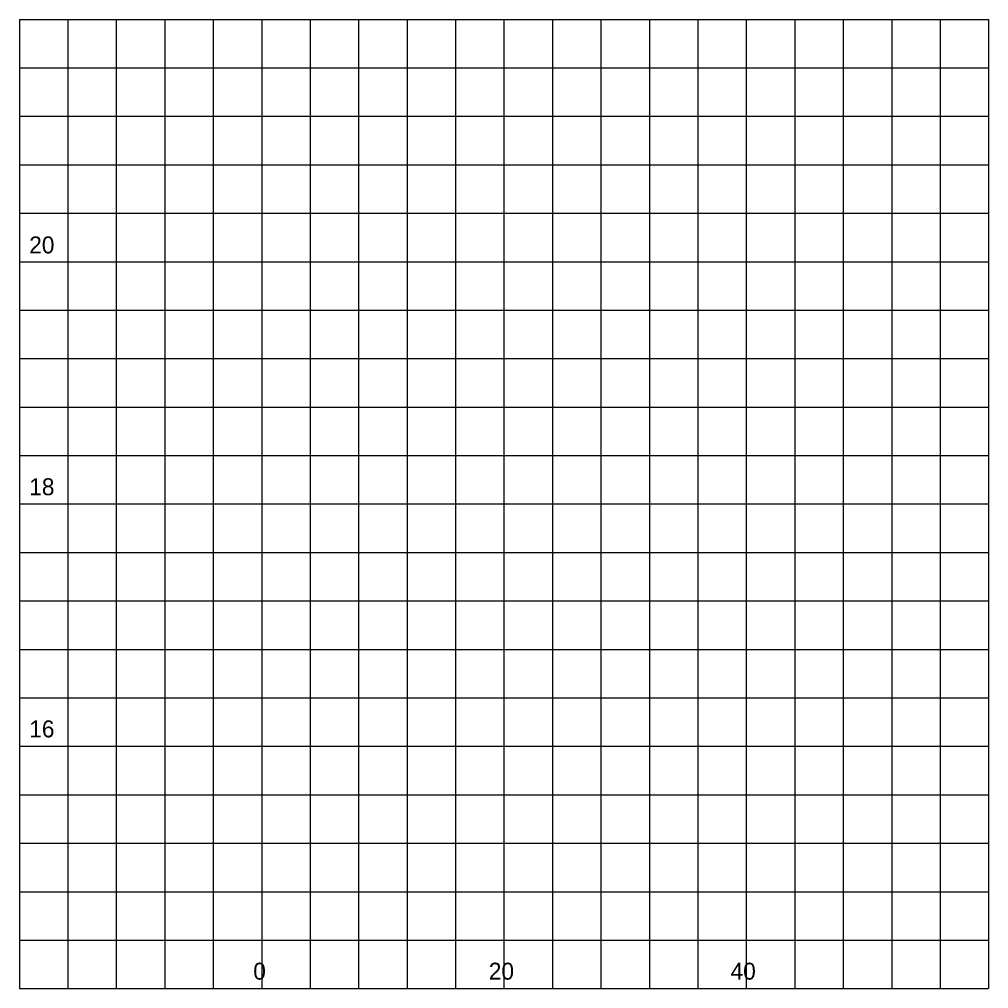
# Model space of a CAD drawing. Extents: x 127723 to 128378, y 21426 to 23736.
# Drawn here: x 127739.5 to 127819.5, y 21531 to 21611 of the extents above; entities that cross this region are included whole.
import ezdxf

# ---------------------------------------------------------------- set-up
doc = ezdxf.new("R2010")
doc.units = 0
for name, color, linetype in [('GroundCover', 7, 'Continuous'), ('Miscellaneous0', 7, 'Continuous'), ('SheetBorder_dp', 7, 'Continuous')]:
    doc.layers.add(name, color=color, linetype=linetype)

msp = doc.modelspace()

# ---------------------------------------------------------------- linework, layer by layer
at = {"layer": 'Miscellaneous0'}
for p, q in [((127743.537, 21610.984), (127743.537, 21530.984)), ((127747.537, 21610.984), (127747.537, 21530.984)), ((127751.537, 21610.984), (127751.537, 21530.984)), ((127755.537, 21610.984), (127755.537, 21530.984)), ((127763.537, 21610.984), (127763.537, 21530.984)), ((127767.537, 21610.984), (127767.537, 21530.984)), ((127771.537, 21610.984), (127771.537, 21530.984)), ((127775.537, 21610.984), (127775.537, 21530.984)), ((127783.537, 21610.984), (127783.537, 21530.984)), ((127787.537, 21610.984), (127787.537, 21530.984)), ((127791.537, 21610.984), (127791.537, 21530.984)), ((127795.537, 21610.984), (127795.537, 21530.984)), ((127803.537, 21610.984), (127803.537, 21530.984)), ((127807.537, 21610.984), (127807.537, 21530.984)), ((127811.537, 21610.984), (127811.537, 21530.984)), ((127815.537, 21610.984), (127815.537, 21530.984)), ((127739.537, 21606.984), (127819.537, 21606.984)), ((127739.537, 21602.984), (127819.537, 21602.984)), ((127739.537, 21598.984), (127819.537, 21598.984)), ((127739.537, 21594.984), (127819.537, 21594.984)), ((127739.537, 21586.984), (127819.537, 21586.984)), ((127739.537, 21582.984), (127819.537, 21582.984)), ((127739.537, 21578.984), (127819.537, 21578.984)), ((127739.537, 21574.984), (127819.537, 21574.984)), ((127739.537, 21566.984), (127819.537, 21566.984)), ((127739.537, 21562.984), (127819.537, 21562.984)), ((127739.537, 21558.984), (127819.537, 21558.984)), ((127739.537, 21554.984), (127819.537, 21554.984)), ((127739.537, 21546.984), (127819.537, 21546.984)), ((127739.537, 21542.984), (127819.537, 21542.984)), ((127739.537, 21538.984), (127819.537, 21538.984)), ((127739.537, 21534.984), (127819.537, 21534.984))]:
    msp.add_line(p, q, dxfattribs=at)
at = {"layer": 'SheetBorder_dp'}
for p, q in [((127739.537, 21610.984), (127819.537, 21610.984)), ((127739.537, 21610.984), (127739.537, 21530.984)), ((127759.537, 21610.984), (127759.537, 21550.984)), ((127759.537, 21610.984), (127759.537, 21530.984)), ((127779.537, 21610.984), (127779.537, 21530.984)), ((127799.537, 21610.984), (127799.537, 21530.984)), ((127819.537, 21610.984), (127819.537, 21530.984)), ((127739.537, 21590.984), (127819.537, 21590.984)), ((127739.537, 21570.984), (127819.537, 21570.984)), ((127739.537, 21550.984), (127819.537, 21550.984)), ((127739.537, 21550.984), (127819.537, 21550.984)), ((127739.537, 21530.984), (127819.537, 21530.984))]:
    msp.add_line(p, q, dxfattribs=at)

# ---------------------------------------------------------------- texts
at = {"layer": 'GroundCover'}
for s, p in [('20', (127740.349, 21591.668)), ('18', (127740.349, 21571.705)), ('16', (127740.349, 21551.722)), ('0', (127758.841, 21531.723)), ('20', (127778.281, 21531.723)), ('40', (127798.237, 21531.723))]:
    msp.add_text(s, height=1.4, dxfattribs=at).set_placement(p)

doc.saveas('drawing.dxf')
